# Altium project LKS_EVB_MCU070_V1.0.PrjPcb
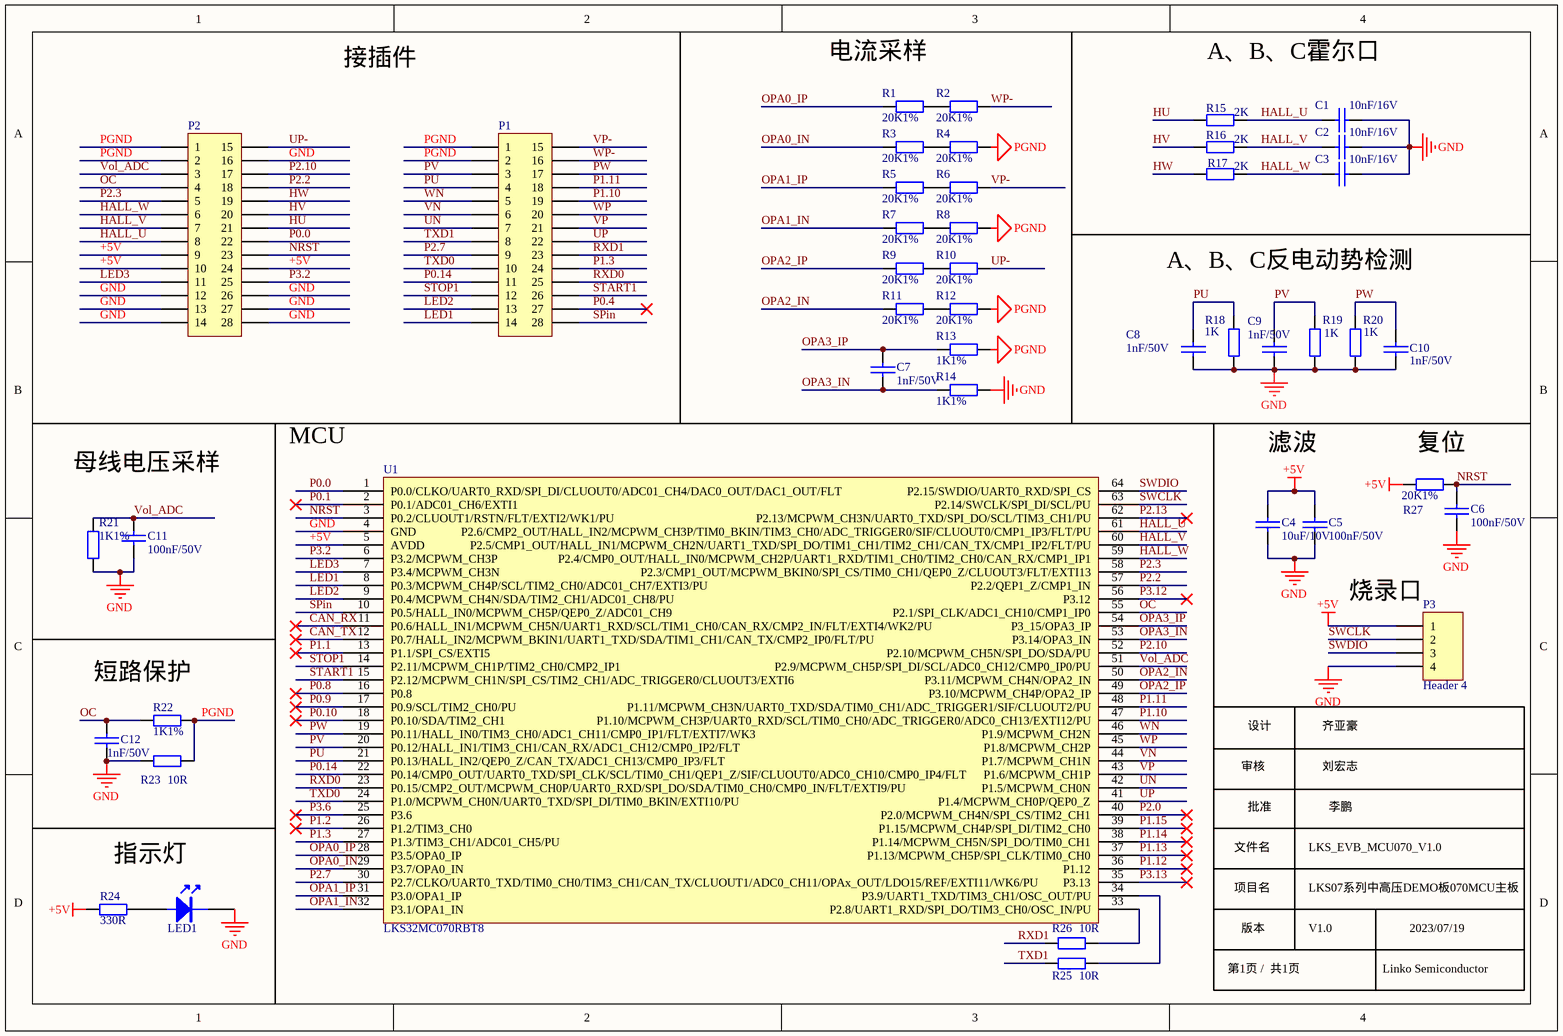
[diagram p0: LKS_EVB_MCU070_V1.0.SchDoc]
1 sheet, 44 parts. Net scope: global (net labels, ports and power ports of the same name join across sheets).
Board file: LKS_EVB_MCU070_V1.0.PcbDoc

## Sheet LKS_EVB_MCU070_V1.0.SchDoc
size A4; SheetNumber: 1; SheetTotal: 1

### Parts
C1  10nF/16V  [0603C]
C2  10nF/16V  [0603C]
C3  10nF/16V  [0603C]
C4  10uF/10V  [0603C]
C5  100nF/50V  [0603C]
C6  100nF/50V  [0603C]
C7  1nF/50V  [0603C]
C8  1nF/50V  [0603C]
C9  1nF/50V  [0603C]
C10  1nF/50V  [0603C]
C11  100nF/50V  [0603C]
C12  1nF/50V  [0603C]
LED1  LED  [LED 0603R]  (value not drawn)
P1  Header 14X2A  [HDR 2X14 底层]  (value not drawn)
P2  Header 14X2A  [HDR 2X14 底层]  (value not drawn)
P3  Header 4  [HDR1X4]
R1  20K1%  [0603R]
R2  20K1%  [0603R]
R3  20K1%  [0603R]
R4  20K1%  [0603R]
R5  20K1%  [0603R]
R6  20K1%  [0603R]
R7  20K1%  [0603R]
R8  20K1%  [0603R]
R9  20K1%  [0603R]
R10  20K1%  [0603R]
R11  20K1%  [0603R]
R12  20K1%  [0603R]
R13  1K1%  [0603R]
R14  1K1%  [0603R]
R15  2K  [0603R]
R16  2K  [0603R]
R17  2K  [0603R]
R18  1K  [0603R]
R19  1K  [0603R]
R20  1K  [0603R]
R21  1K1%  [0603R]
R22  1K1%  [0603R]
R23  10R  [0603R]
R24  330R  [0603R]
R25  10R  [0603R]
R26  10R  [0603R]
R27  20K1%  [0603R]
U1  LKS32MC070RBT8  [LQFP64]

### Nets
+5V: C4.2 C5.2 P2.9 P2.10 P2.24 P3.1 R24.1 R27.2 U1.5(AVDD)
GND: C1.2 C2.2 C3.2 C4.1 C5.1 C6.2 C8.2 C9.2 C10.2 C11.1 C12.1 LED1.2(K) P2.12 P2.13 P2.14 P2.16 P2.26 P2.27 P2.28 P3.4 R14.1 R18.2 R19.2 R20.2 R21.1 R23.2 U1.4(GND)
PGND: P1.1 P1.2 P2.1 P2.2 R4.1 R8.1 R12.1 R13.1 R22.2 R23.1
CAN_RX: U1.11(P0.6/HALL_IN1/MCPWM_CH5N/UART1_RXD/SCL/TIM1_CH0/CAN_RX/CMP2_IN/FLT/EXTI4/WK2/PU)
CAN_TX: U1.12(P0.7/HALL_IN2/MCPWM_BKIN1/UART1_TXD/SDA/TIM1_CH1/CAN_TX/CMP2_IP0/FLT/PU)
HALL_U: C1.1 P2.8 R15.2 U1.61(P2.6/CMP2_OUT/HALL_IN2/MCPWM_CH3P/TIM0_BKIN/TIM3_CH0/ADC_TRIGGER0/SIF/CLUOUT0/CMP1_IP3/FLT/PU)
HALL_V: C2.1 P2.7 R16.2 U1.60(P2.5/CMP1_OUT/HALL_IN1/MCPWM_CH2N/UART1_TXD/SPI_DO/TIM1_CH1/TIM2_CH1/CAN_TX/CMP1_IP2/FLT/PU)
HALL_W: C3.1 P2.6 R17.2 U1.59(P2.4/CMP0_OUT/HALL_IN0/MCPWM_CH2P/UART1_RXD/TIM1_CH0/TIM2_CH0/CAN_RX/CMP1_IP1)
HU: P2.21 R15.1
HV: P2.20 R16.1
HW: P2.19 R17.1
LED1: P1.14 U1.8(P0.3/MCPWM_CH4P/SCL/TIM2_CH0/ADC01_CH7/EXTI3/PU)
LED2: P1.13 U1.9(P0.4/MCPWM_CH4N/SDA/TIM2_CH1/ADC01_CH8/PU)
LED3: P2.11 U1.7(P3.4/MCPWM_CH3N)
NRST: C6.1 P2.23 R27.1 U1.3(P0.2/CLUOUT1/RSTN/FLT/EXTI2/WK1/PU)
OC: C12.2 P2.4 R22.1 U1.55(P2.1/SPI_CLK/ADC1_CH10/CMP1_IP0)
OPA0_IN: R3.2 U1.29(P3.7/OPA0_IN)
OPA0_IP: R1.2 U1.28(P3.5/OPA0_IP)
OPA1_IN: R7.2 U1.32(P3.1/OPA1_IN)
OPA1_IP: R5.2 U1.31(P3.0/OPA1_IP)
OPA2_IN: R11.2 U1.50(P3.11/MCPWM_CH4N/OPA2_IN)
OPA2_IP: R9.2 U1.49(P3.10/MCPWM_CH4P/OPA2_IP)
OPA3_IN: C7.2 R14.2 U1.53(P3.14/OPA3_IN)
OPA3_IP: C7.1 R13.2 U1.54(P3_15/OPA3_IP)
P0.0: P2.22 U1.1(P0.0/CLKO/UART0_RXD/SPI_DI/CLUOUT0/ADC01_CH4/DAC0_OUT/DAC1_OUT/FLT)
P0.1: U1.2(P0.1/ADC01_CH6/EXTI1)
P0.4: P1.27
P0.8: U1.16(P0.8)
P0.9: U1.17(P0.9/SCL/TIM2_CH0/PU)
P0.10: U1.18(P0.10/SDA/TIM2_CH1)
P0.14: P1.11 U1.22(P0.14/CMP0_OUT/UART0_TXD/SPI_CLK/SCL/TIM0_CH1/QEP1_Z/SIF/CLUOUT0/ADC0_CH10/CMP0_IP4/FLT)
P1.1: U1.13(P1.1/SPI_CS/EXTI5)
P1.2: U1.26(P1.2/TIM3_CH0)
P1.3: P1.24 U1.27(P1.3/TIM3_CH1/ADC01_CH5/PU)
P1.10: P1.19 U1.47(P1.10/MCPWM_CH3P/UART0_RXD/SCL/TIM0_CH0/ADC_TRIGGER0/ADC0_CH13/EXTI12/PU)
P1.11: P1.18 U1.48(P1.11/MCPWM_CH3N/UART0_TXD/SDA/TIM0_CH1/ADC_TRIGGER1/SIF/CLUOUT2/PU)
P1.12: U1.36(P1.12)
P1.13: U1.37(P1.13/MCPWM_CH5P/SPI_CLK/TIM0_CH0)
P1.14: U1.38(P1.14/MCPWM_CH5N/SPI_DO/TIM0_CH1)
P1.15: U1.39(P1.15/MCPWM_CH4P/SPI_DI/TIM2_CH0)
P2.0: U1.40(P2.0/MCPWM_CH4N/SPI_CS/TIM2_CH1)
P2.2: P2.18 U1.57(P2.2/QEP1_Z/CMP1_IN)
P2.3: P2.5 U1.58(P2.3/CMP1_OUT/MCPWM_BKIN0/SPI_CS/TIM0_CH1/QEP0_Z/CLUOUT3/FLT/EXTI13)
P2.7: P1.9 U1.30(P2.7/CLKO/UART0_TXD/TIM0_CH0/TIM3_CH1/CAN_TX/CLUOUT1/ADC0_CH11/OPAx_OUT/LDO15/REF/EXTI11/WK6/PU)
P2.10: P2.17 U1.52(P2.10/MCPWM_CH5N/SPI_DO/SDA/PU)
P2.13: U1.62(P2.13/MCPWM_CH3N/UART0_TXD/SPI_DO/SCL/TIM3_CH1/PU)
P3.2: P2.25 U1.6(P3.2/MCPWM_CH3P)
P3.6: U1.25(P3.6)
P3.12: U1.56(P3.12)
P3.13: U1.35(P3.13)
PU: C8.1 P1.4 R18.1 U1.21(P0.13/HALL_IN2/QEP0_Z/CAN_TX/ADC1_CH13/CMP0_IP3/FLT)
PV: C9.1 P1.3 R19.1 U1.20(P0.12/HALL_IN1/TIM3_CH1/CAN_RX/ADC1_CH12/CMP0_IP2/FLT)
PW: C10.1 P1.17 R20.1 U1.19(P0.11/HALL_IN0/TIM3_CH0/ADC1_CH11/CMP0_IP1/FLT/EXTI7/WK3)
RXD0: P1.25 U1.23(P0.15/CMP2_OUT/MCPWM_CH0P/UART0_RXD/SPI_DO/SDA/TIM0_CH0/CMP0_IN/FLT/EXTI9/PU)
RXD1: P1.23 R26.2
SPin: P1.28 U1.10(P0.5/HALL_IN0/MCPWM_CH5P/QEP0_Z/ADC01_CH9)
START1: P1.26 U1.15(P2.12/MCPWM_CH1N/SPI_CS/TIM2_CH1/ADC_TRIGGER0/CLUOUT3/EXTI6)
STOP1: P1.12 U1.14(P2.11/MCPWM_CH1P/TIM2_CH0/CMP2_IP1)
SWCLK: P3.2 U1.63(P2.14/SWCLK/SPI_DI/SCL/PU)
SWDIO: P3.3 U1.64(P2.15/SWDIO/UART0_RXD/SPI_CS)
TXD0: P1.10 U1.24(P1.0/MCPWM_CH0N/UART0_TXD/SPI_DI/TIM0_BKIN/EXTI10/PU)
TXD1: P1.8 R25.2
UN: P1.7 U1.42(P1.5/MCPWM_CH0N)
UP: P1.22 U1.41(P1.4/MCPWM_CH0P/QEP0_Z)
UP-: P2.15 R10.1
VN: P1.6 U1.44(P1.7/MCPWM_CH1N)
Vol_ADC: C11.2 P2.3 R21.2 U1.51(P2.9/MCPWM_CH5P/SPI_DI/SCL/ADC0_CH12/CMP0_IP0/PU)
VP: P1.21 U1.43(P1.6/MCPWM_CH1P)
VP-: P1.15 R6.1
WN: P1.5 U1.46(P1.9/MCPWM_CH2N)
WP: P1.20 U1.45(P1.8/MCPWM_CH2P)
WP-: P1.16 R2.1
NetLED1_1: LED1.1(A) R24.2
NetR1_1: R1.1 R2.2
NetR3_1: R3.1 R4.2
NetR5_1: R5.1 R6.2
NetR7_1: R7.1 R8.2
NetR9_1: R9.1 R10.2
NetR11_1: R11.1 R12.2
NetR25_1: R25.1 U1.34(P3.9/UART1_TXD/TIM3_CH1/OSC_OUT/PU)
NetR26_1: R26.1 U1.33(P2.8/UART1_RXD/SPI_DO/TIM3_CH0/OSC_IN/PU)

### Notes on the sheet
- 接插件
- 母线电压采样
- 滤波
- (near R27) 复位
- 烧录口
- 短路保护
- 审核
- 设计
- 刘宏志
- 齐亚豪
- 文件名
- 批准
- LKS_EVB_MCU070_V1.0
- 李鹏
- 指示灯
- 项目名
- LKS07系列中高压DEMO板070MCU主板
- 第1页 /  共1页
- 版本
- V1.0
- Linko Semiconductor
- 2023/07/19
- Labels drawn without touching a wire or pin: A、B、C反电动势检测, A、B、C霍尔口, MCU, 电流采样

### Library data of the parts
C1-C3 C8-C10 = CAP: Capacitor
C4-C7 C11 C12 = C: Capacitor
LED1 = LED: LED_Light
P1 P2 = Header 14X2A: Header, 14-Pin, Dual row
P3 = Header 4: Header, 4-Pin
R1-R27 = Res: Resistor; Value: K
U1 = LKS32MC070RBT8: 芯片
